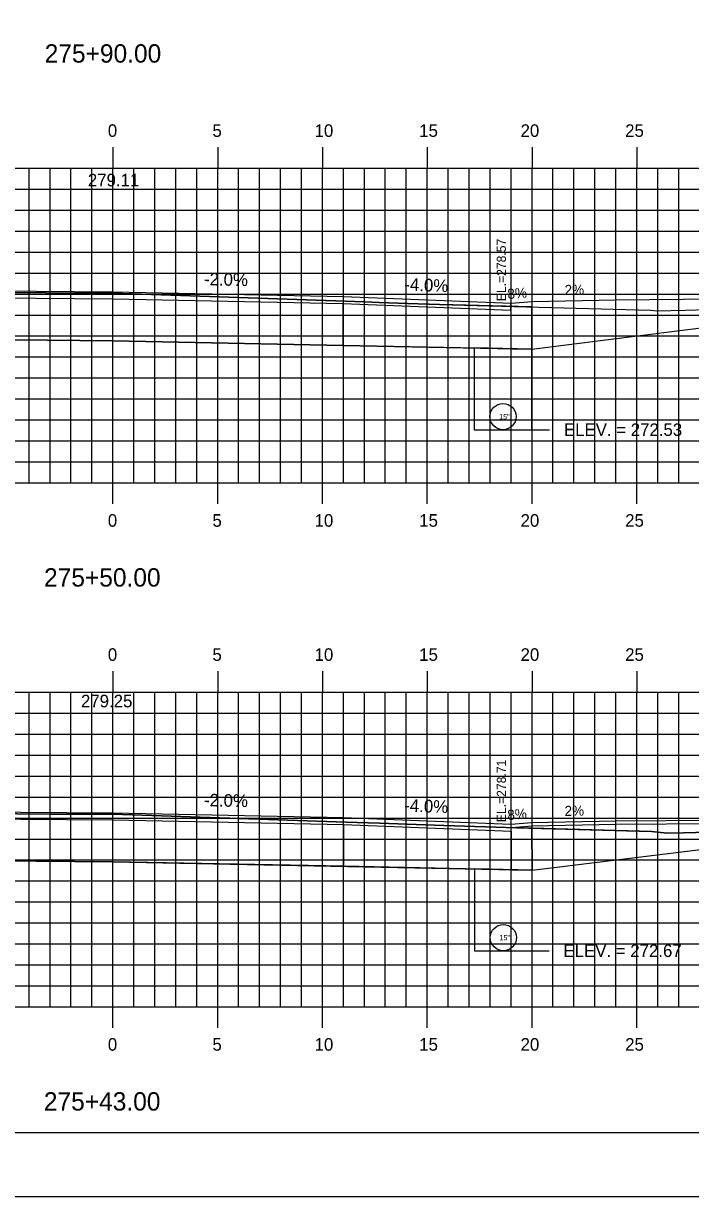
# Model space of a CAD drawing. Extents: x 853563 to 853733, y 366268 to 366378.
# Drawn here: x 853641.5 to 853673.3, y 366268.2 to 366324.1 of the extents above; entities that cross this region are included whole.
import ezdxf

# ---------------------------------------------------------------- set-up
doc = ezdxf.new("R2010")
doc.units = 0
for name, color, linetype in [('ANNOTATION', 7, 'Continuous'), ('BORDER', 7, 'Continuous'), ('D_Roadway_Centerline_Text', 7, 'Continuous'), ('D_Roadway_Drive_Gravel_RT', 7, 'Continuous'), ('D_Roadway_Drive_SubGrade', 7, 'Continuous'), ('D_Roadway_Edge_TW', 7, 'Continuous'), ('D_Roadway_SubGrade', 7, 'Continuous'), ('D_Text_Standard', 7, 'Continuous'), ('H_V ANNOTATION', 7, 'Continuous'), ('JUNK COM EXC', 7, 'Continuous'), ('junk strct exc', 7, 'Continuous'), ('MAJOR', 7, 'Continuous'), ('MINOR', 7, 'Continuous'), ('PDRAIN', 7, 'Continuous'), ('PLOT BOUNDARY', 7, 'Continuous'), ('S_Roadway_Centerline', 7, 'Continuous')]:
    doc.layers.add(name, color=color, linetype=linetype)

msp = doc.modelspace()

# ---------------------------------------------------------------- linework, layer by layer
at = {"layer": 'BORDER'}
msp.add_line((853570.768, 366271.236), (853730.768, 366271.236), dxfattribs=at)
at = {"layer": 'D_Roadway_Drive_Gravel_RT'}
for p, q in [((853669.768, 366310.963), (853697.603, 366311.267)), ((853664.768, 366310.803), (853665.768, 366310.883)), ((853664.768, 366310.803), (853665.768, 366310.883)), ((853665.768, 366310.883), (853669.768, 366310.963)), ((853664.764, 366285.946), (853665.764, 366286.026)), ((853665.764, 366286.026), (853669.764, 366286.106)), ((853669.764, 366286.106), (853697.603, 366286.284)), ((853669.765, 366285.939), (853697.603, 366286.117)), ((853664.774, 366285.779), (853665.773, 366285.859)), ((853665.773, 366285.859), (853669.768, 366285.939))]:
    msp.add_line(p, q, dxfattribs=at)
at = {"layer": 'D_Roadway_Drive_SubGrade'}
for p, q in [((853665.758, 366308.61), (853675.768, 366309.862)), ((853664.758, 366308.63), (853665.758, 366308.61)), ((853665.774, 366283.753), (853675.768, 366284.977)), ((853664.774, 366283.773), (853665.774, 366283.753))]:
    msp.add_line(p, q, dxfattribs=at)
at = {"layer": 'D_Roadway_Edge_TW'}
for points in [[(853626.768, 366311.122), (853634.768, 366311.442), (853645.768, 366311.343), (853656.768, 366311.123), (853664.768, 366310.803)], [(853624.319, 366286.151), (853634.768, 366286.569), (853645.768, 366286.486), (853656.768, 366286.266), (853664.764, 366285.946)]]:
    msp.add_lwpolyline(points, dxfattribs=at)
at = {"layer": 'D_Roadway_SubGrade'}
for p, q in [((853664.758, 366310.47), (853664.758, 366310.804)), ((853664.774, 366285.613), (853664.774, 366285.946))]:
    msp.add_line(p, q, dxfattribs=at)
for points in [[(853634.758, 366309.109), (853634.758, 366311.109), (853645.758, 366311.01), (853656.758, 366310.79), (853656.758, 366308.79), (853645.758, 366309.01)], [(853656.758, 366310.79), (853664.758, 366310.47), (853664.758, 366308.63), (853656.758, 366308.79)], [(853634.773, 366284.236), (853634.773, 366286.236), (853645.773, 366286.153), (853656.773, 366285.933), (853656.773, 366283.933), (853645.773, 366284.153)], [(853656.773, 366285.933), (853664.774, 366285.613), (853664.774, 366283.773), (853656.773, 366283.933)]]:
    msp.add_lwpolyline(points, close=True, dxfattribs=at)
at = {"layer": 'D_Text_Standard'}
for points in [[(853665.758, 366304.766), (853665.93, 366304.766), (853666.61, 366304.766)], [(853665.774, 366279.906), (853665.908, 366279.906), (853666.588, 366279.906)]]:
    msp.add_lwpolyline(points, dxfattribs=at)
at = {"layer": 'JUNK COM EXC'}
for points in [[(853620.187, 366310.842), (853620.187, 366308.817), (853626.758, 366308.949), (853634.758, 366309.109), (853645.758, 366309.01), (853656.758, 366308.79), (853665.758, 366308.61), (853665.766, 366310.621), (853661.346, 366310.741), (853659.822, 366310.792), (853658.471, 366310.84), (853657.772, 366310.858), (853645.768, 366311.281), (853644.236, 366311.274), (853640.891, 366311.31), (853634.333, 366311.383), (853628.855, 366311.175), (853627.053, 366311.098), (853626.465, 366311.121), (853622.365, 366311.115), (853620.187, 366310.842)], [(853623.319, 366286.204), (853623.319, 366284.007), (853634.773, 366284.236), (853645.773, 366284.153), (853665.774, 366283.753), (853665.766, 366285.75), (853665.022, 366285.77), (853661.556, 366285.887), (853658.484, 366285.994), (853656.892, 366286.036), (853645.768, 366286.428), (853642.801, 366286.415), (853636.324, 366286.484), (853634.272, 366286.506), (853631.226, 366286.391), (853627.091, 366286.231), (853625.703, 366286.207), (853623.319, 366286.204)], [(853697.603, 366285.117), (853697.603, 366286.284), (853684.27, 366285.84), (853672.991, 366285.531), (853672.225, 366285.511), (853671.472, 366285.595), (853665.766, 366285.75), (853665.774, 366283.753), (853675.768, 366284.977), (853697.603, 366285.117)]]:
    msp.add_lwpolyline(points, dxfattribs=at)
at = {"layer": 'junk strct exc'}
for points in [[(853663.008, 366308.665), (853663.008, 366304.766), (853665.758, 366304.766), (853665.758, 366308.61)], [(853663.024, 366283.808), (853663.024, 366279.906), (853665.774, 366279.906), (853665.774, 366283.753)]]:
    msp.add_lwpolyline(points, close=True, dxfattribs=at)
at = {"layer": 'MAJOR'}
for p, q in [((853645.768, 366318.238), (853645.768, 366317.236)), ((853650.768, 366318.238), (853650.768, 366317.236)), ((853655.768, 366318.238), (853655.768, 366317.236)), ((853660.768, 366318.238), (853660.768, 366317.236)), ((853665.768, 366318.238), (853665.768, 366317.236)), ((853670.768, 366318.238), (853670.768, 366317.236)), ((853575.768, 366317.236), (853715.768, 366317.236)), ((853575.768, 366317.236), (853715.768, 366317.236)), ((853645.768, 366302.236), (853645.768, 366317.236)), ((853650.768, 366302.236), (853650.768, 366317.236)), ((853655.768, 366302.236), (853655.768, 366317.236)), ((853660.768, 366302.236), (853660.768, 366317.236)), ((853665.768, 366302.236), (853665.768, 366317.236)), ((853670.768, 366302.236), (853670.768, 366317.236)), ((853575.768, 366312.236), (853715.768, 366312.236)), ((853575.768, 366307.236), (853715.768, 366307.236)), ((853575.768, 366302.236), (853715.768, 366302.236)), ((853575.768, 366302.236), (853715.768, 366302.236)), ((853645.768, 366301.234), (853645.768, 366302.236)), ((853650.768, 366301.234), (853650.768, 366302.236)), ((853655.768, 366301.234), (853655.768, 366302.236)), ((853660.768, 366301.234), (853660.768, 366302.236)), ((853665.768, 366301.234), (853665.768, 366302.236)), ((853670.768, 366301.234), (853670.768, 366302.236)), ((853645.768, 366293.238), (853645.768, 366292.236)), ((853650.768, 366293.238), (853650.768, 366292.236)), ((853655.768, 366293.238), (853655.768, 366292.236)), ((853660.768, 366293.238), (853660.768, 366292.236)), ((853665.768, 366293.238), (853665.768, 366292.236)), ((853670.768, 366293.238), (853670.768, 366292.236)), ((853575.768, 366292.236), (853715.768, 366292.236)), ((853575.768, 366292.236), (853715.768, 366292.236)), ((853645.768, 366277.236), (853645.768, 366292.236)), ((853650.768, 366277.236), (853650.768, 366292.236)), ((853655.768, 366277.236), (853655.768, 366292.236)), ((853660.768, 366277.236), (853660.768, 366292.236)), ((853665.768, 366277.236), (853665.768, 366292.236)), ((853670.768, 366277.236), (853670.768, 366292.236)), ((853575.768, 366287.236), (853715.768, 366287.236)), ((853575.768, 366282.236), (853715.768, 366282.236)), ((853575.768, 366277.236), (853715.768, 366277.236)), ((853575.768, 366277.236), (853715.768, 366277.236)), ((853645.768, 366276.234), (853645.768, 366277.236)), ((853650.768, 366276.234), (853650.768, 366277.236)), ((853655.768, 366276.234), (853655.768, 366277.236)), ((853660.768, 366276.234), (853660.768, 366277.236)), ((853665.768, 366276.234), (853665.768, 366277.236)), ((853670.768, 366276.234), (853670.768, 366277.236))]:
    msp.add_line(p, q, dxfattribs=at)
at = {"layer": 'MINOR'}
for p, q in [((853641.768, 366302.236), (853641.768, 366317.236)), ((853642.768, 366302.236), (853642.768, 366317.236)), ((853643.768, 366302.236), (853643.768, 366317.236)), ((853644.768, 366302.236), (853644.768, 366317.236)), ((853646.768, 366302.236), (853646.768, 366317.236)), ((853647.768, 366302.236), (853647.768, 366317.236)), ((853648.768, 366302.236), (853648.768, 366317.236)), ((853649.768, 366302.236), (853649.768, 366317.236)), ((853651.768, 366302.236), (853651.768, 366317.236)), ((853652.768, 366302.236), (853652.768, 366317.236)), ((853653.768, 366302.236), (853653.768, 366317.236)), ((853654.768, 366302.236), (853654.768, 366317.236)), ((853656.768, 366302.236), (853656.768, 366317.236)), ((853657.768, 366302.236), (853657.768, 366317.236)), ((853658.768, 366302.236), (853658.768, 366317.236)), ((853659.768, 366302.236), (853659.768, 366317.236)), ((853661.768, 366302.236), (853661.768, 366317.236)), ((853662.768, 366302.236), (853662.768, 366317.236)), ((853663.768, 366302.236), (853663.768, 366317.236)), ((853664.768, 366302.236), (853664.768, 366317.236)), ((853666.768, 366302.236), (853666.768, 366317.236)), ((853667.768, 366302.236), (853667.768, 366317.236)), ((853668.768, 366302.236), (853668.768, 366317.236)), ((853669.768, 366302.236), (853669.768, 366317.236)), ((853671.768, 366302.236), (853671.768, 366317.236)), ((853672.768, 366302.236), (853672.768, 366317.236)), ((853575.768, 366316.236), (853715.768, 366316.236)), ((853575.768, 366315.236), (853715.768, 366315.236)), ((853575.768, 366314.236), (853715.768, 366314.236)), ((853575.768, 366313.236), (853715.768, 366313.236)), ((853575.768, 366311.236), (853715.768, 366311.236)), ((853575.768, 366310.236), (853715.768, 366310.236)), ((853575.768, 366309.236), (853715.768, 366309.236)), ((853575.768, 366308.236), (853715.768, 366308.236)), ((853575.768, 366306.236), (853715.768, 366306.236)), ((853575.768, 366305.236), (853715.768, 366305.236)), ((853575.768, 366304.236), (853715.768, 366304.236)), ((853575.768, 366303.236), (853715.768, 366303.236)), ((853641.768, 366277.236), (853641.768, 366292.236)), ((853642.768, 366277.236), (853642.768, 366292.236)), ((853643.768, 366277.236), (853643.768, 366292.236)), ((853644.768, 366277.236), (853644.768, 366292.236)), ((853646.768, 366277.236), (853646.768, 366292.236)), ((853647.768, 366277.236), (853647.768, 366292.236)), ((853648.768, 366277.236), (853648.768, 366292.236)), ((853649.768, 366277.236), (853649.768, 366292.236)), ((853651.768, 366277.236), (853651.768, 366292.236)), ((853652.768, 366277.236), (853652.768, 366292.236)), ((853653.768, 366277.236), (853653.768, 366292.236)), ((853654.768, 366277.236), (853654.768, 366292.236)), ((853656.768, 366277.236), (853656.768, 366292.236)), ((853657.768, 366277.236), (853657.768, 366292.236)), ((853658.768, 366277.236), (853658.768, 366292.236)), ((853659.768, 366277.236), (853659.768, 366292.236)), ((853661.768, 366277.236), (853661.768, 366292.236)), ((853662.768, 366277.236), (853662.768, 366292.236)), ((853663.768, 366277.236), (853663.768, 366292.236)), ((853664.768, 366277.236), (853664.768, 366292.236)), ((853666.768, 366277.236), (853666.768, 366292.236)), ((853667.768, 366277.236), (853667.768, 366292.236)), ((853668.768, 366277.236), (853668.768, 366292.236)), ((853669.768, 366277.236), (853669.768, 366292.236)), ((853671.768, 366277.236), (853671.768, 366292.236)), ((853672.768, 366277.236), (853672.768, 366292.236)), ((853575.768, 366291.236), (853715.768, 366291.236)), ((853575.768, 366290.236), (853715.768, 366290.236)), ((853575.768, 366289.236), (853715.768, 366289.236)), ((853575.768, 366288.236), (853715.768, 366288.236)), ((853575.768, 366286.236), (853715.768, 366286.236)), ((853575.768, 366285.236), (853715.768, 366285.236)), ((853575.768, 366284.236), (853715.768, 366284.236)), ((853575.768, 366283.236), (853715.768, 366283.236)), ((853575.768, 366281.236), (853715.768, 366281.236)), ((853575.768, 366280.236), (853715.768, 366280.236)), ((853575.768, 366279.236), (853715.768, 366279.236)), ((853575.768, 366278.236), (853715.768, 366278.236))]:
    msp.add_line(p, q, dxfattribs=at)
at = {"layer": 'PDRAIN'}
for points in [[(853663.008, 366308.665), (853663.008, 366304.766), (853665.758, 366304.766), (853665.758, 366308.61)], [(853663.024, 366283.808), (853663.024, 366279.906), (853665.774, 366279.906), (853665.774, 366283.753)]]:
    msp.add_lwpolyline(points, dxfattribs=at)
for centre in [(853664.383, 366305.391), (853664.399, 366280.531)]:
    msp.add_circle(centre, 0.625, dxfattribs=at)
at = {"layer": 'PLOT BOUNDARY'}
msp.add_lwpolyline([(853562.674, 366268.177), (853732.674, 366268.177), (853732.674, 366378.177), (853562.674, 366378.177)], close=True, dxfattribs=at)
at = {"layer": 'S_Roadway_Centerline'}
for points in [[(853640.891, 366311.31), (853644.236, 366311.274), (853645.768, 366311.281), (853657.772, 366310.858), (853658.471, 366310.84), (853659.822, 366310.792), (853661.346, 366310.741), (853671.435, 366310.467), (853671.721, 366310.435), (853673.078, 366310.47), (853676.362, 366310.56)], [(853598.769, 366284.407), (853604.894, 366284.377), (853606.698, 366284.265), (853611.003, 366284.182), (853611.419, 366284.161), (853611.982, 366284.229), (853616.436, 366285.423), (853619.173, 366285.808), (853622.326, 366286.202), (853625.703, 366286.207), (853627.091, 366286.231), (853631.226, 366286.391), (853634.272, 366286.506), (853636.324, 366286.484), (853642.801, 366286.415), (853645.768, 366286.428), (853656.892, 366286.036), (853658.484, 366285.994), (853661.556, 366285.887), (853665.022, 366285.77), (853671.472, 366285.595), (853672.225, 366285.511), (853672.991, 366285.531), (853684.27, 366285.84)]]:
    msp.add_lwpolyline(points, dxfattribs=at)

# ---------------------------------------------------------------- texts
at = {"layer": 'ANNOTATION'}
for s, rotation, p in [('-2.0%', 358.8542, (853650.111, 366311.657)), ('-4.0%', 357.7094, (853659.664, 366311.408)), ('-2.0%', 358.8542, (853650.111, 366286.799)), ('-4.0%', 357.7097, (853659.661, 366286.551))]:
    msp.add_text(s, height=0.6, rotation=rotation, dxfattribs=at).set_placement(p)
at = {"layer": 'D_Roadway_Centerline_Text'}
for s, p in [('279.11', (853644.574, 366316.375)), ('279.25', (853644.245, 366291.518))]:
    msp.add_text(s, height=0.6, dxfattribs=at).set_placement(p)
at = {"layer": 'D_Roadway_Drive_Gravel_RT'}
for s, rotation, p in [('8%', 4.5739, (853664.615, 366310.997)), ('8%', 4.5739, (853664.615, 366310.997)), ('2%', 1.1922, (853667.33, 366311.192)), ('8%', 4.5739, (853664.612, 366286.139)), ('2%', 1.1922, (853667.327, 366286.334))]:
    msp.add_text(s, height=0.48, rotation=rotation, dxfattribs=at).set_placement(p)
at = {"layer": 'D_Text_Standard'}
for s, p in [(' EL.=278.57', (853664.522, 366310.734)), (' EL.=278.71', (853664.522, 366285.877))]:
    msp.add_text(s, height=0.4335, rotation=90, dxfattribs=at).set_placement(p)
for s, p in [('ELEV. = 272.53', (853667.29, 366304.466)), ('ELEV. = 272.67', (853667.268, 366279.606))]:
    msp.add_text(s, height=0.6, dxfattribs=at).set_placement(p)
at = {"layer": 'H_V ANNOTATION'}
for s, height, p in [('275+90.00', 0.875, (853642.513, 366322.28)), ('0', 0.6, (853645.527, 366318.736)), ('5', 0.6, (853650.519, 366318.736)), ('10', 0.6, (853655.393, 366318.736)), ('15', 0.6, (853660.385, 366318.736)), ('20', 0.6, (853665.222, 366318.736)), ('25', 0.6, (853670.213, 366318.736)), ('0', 0.6, (853645.527, 366300.136)), ('5', 0.6, (853650.519, 366300.136)), ('10', 0.6, (853655.393, 366300.136)), ('15', 0.6, (853660.385, 366300.136)), ('20', 0.6, (853665.222, 366300.136)), ('25', 0.6, (853670.213, 366300.136)), ('275+50.00', 0.875, (853642.482, 366297.28)), ('0', 0.6, (853645.527, 366293.736)), ('5', 0.6, (853650.519, 366293.736)), ('10', 0.6, (853655.393, 366293.736)), ('15', 0.6, (853660.385, 366293.736)), ('20', 0.6, (853665.222, 366293.736)), ('25', 0.6, (853670.213, 366293.736)), ('0', 0.6, (853645.527, 366275.136)), ('5', 0.6, (853650.519, 366275.136)), ('10', 0.6, (853655.393, 366275.136)), ('15', 0.6, (853660.385, 366275.136)), ('20', 0.6, (853665.222, 366275.136)), ('25', 0.6, (853670.213, 366275.136)), ('275+43.00', 0.875, (853642.474, 366272.28))]:
    msp.add_text(s, height=height, dxfattribs=at).set_placement(p)
at = {"layer": 'PDRAIN'}
for p in [(853664.196, 366305.266), (853664.212, 366280.406)]:
    msp.add_text('15"', height=0.25, dxfattribs=at).set_placement(p)
at = {"layer": 'S_Roadway_Centerline'}
for s, p in [('C', (853645.762, 366311.281)), ('L', (853645.768, 366311.274)), ('C', (853645.762, 366286.428)), ('L', (853645.768, 366286.421))]:
    msp.add_text(s, height=0.0146, dxfattribs=at).set_placement(p)

doc.saveas('drawing.dxf')
